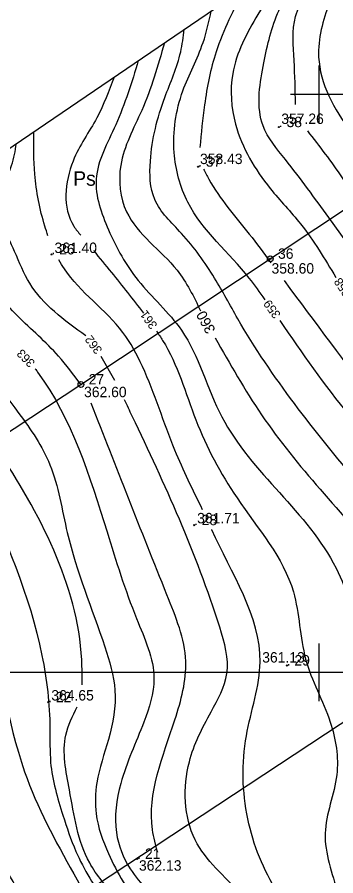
# Model space of a CAD drawing. Extents: x 4632591 to 4651936, y 5351032 to 5369988.
# Drawn here: x 4638423.8 to 4638451.4, y 5357982.4 to 5358056.7 of the extents above; entities that cross this region are included whole.
import ezdxf

# ---------------------------------------------------------------- set-up
doc = ezdxf.new("R2010")
doc.units = 0
for name, color, linetype in [('EDZPD_219', 7, 'Continuous'), ('EDZPP_202', 7, 'Continuous'), ('EKLPK_209', 7, 'Continuous'), ('Warstwa 40', 7, 'Continuous'), ('Warstwa 60', 7, 'Continuous'), ('Warstwa 62', 7, 'Continuous'), ('WUKPS_403', 7, 'Continuous'), ('WWRPH_811', 7, 'Continuous'), ('WWRPH_812', 7, 'Continuous'), ('WWRPH_814', 7, 'Continuous')]:
    doc.layers.add(name, color=color, linetype=linetype)

msp = doc.modelspace()

# ---------------------------------------------------------------- linework, layer by layer
at = {"layer": 'EDZPD_219'}
for p, q in [((4638429.37, 5358024.9), (4638519.216149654, 5358084.48679968)), ((4638419.0200000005, 5358018.09), (4638429.37, 5358024.9)), ((4638428.49, 5357980.16), (4638470.0200000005, 5358007.53))]:
    msp.add_line(p, q, dxfattribs=at)
at = {"layer": 'EDZPP_202'}
for centre in [(4638445.76, 5358035.7700000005), (4638429.37, 5358024.9)]:
    msp.add_circle(centre, 0.25, dxfattribs=at)
at = {"layer": 'Warstwa 40'}
msp.add_line((4638385.83184923, 5358019.9472410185), (4638506.884176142, 5358102.232810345), dxfattribs=at)
at = {"layer": 'Warstwa 60'}
for p, q in [((4638450, 5358047.5), (4638450, 5358052.5)), ((4638447.5, 5358050), (4638452.5, 5358050)), ((4638450, 5358000), (4638450, 5358002.5)), ((4638400, 5358000), (4638516.95102771, 5358000)), ((4638450, 5357997.5), (4638450, 5358000))]:
    msp.add_line(p, q, dxfattribs=at)
at = {"layer": 'WUKPS_403'}
for centre in [(4638446.5, 5358047.16), (4638439.51, 5358043.74), (4638426.82, 5358036.15), (4638445.76, 5358035.770000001), (4638429.37, 5358024.9), (4638439.16, 5358012.73), (4638447.18, 5358000.59), (4638426.53, 5357997.41), (4638434.24, 5357983.86)]:
    msp.add_circle(centre, 0.045, dxfattribs=at)
at = {"layer": 'WWRPH_811'}
msp.add_line((4638432.28977861, 5358025.23095936), (4638431.11162308, 5358027.317935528), dxfattribs=at)
for points in [[(4638447.943284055, 5358049.128498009), (4638447.819581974, 5358052.914616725), (4638447.944636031, 5358056.728765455), (4638450.195609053, 5358060.480387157), (4638451.633730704, 5358062.918941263), (4638452.356480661, 5358065.167496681)], [(4638448.371201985, 5358062.458495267), (4638444.693230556, 5358056.916346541), (4638442.504784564, 5358051.789130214), (4638442.754892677, 5358047.412238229), (4638445.756190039, 5358041.847332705), (4638448.38232523, 5358038.783508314), (4638451.428718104, 5358034.16460043)], [(4638445.308489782, 5358032.232813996), (4638443.942906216, 5358034.093981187), (4638438.628108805, 5358040.659319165), (4638437.440095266, 5358044.973684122), (4638438.190419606, 5358050.2884815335), (4638439.9411764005, 5358054.477792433), (4638440.652073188, 5358057.211401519)], [(4638432.23553517, 5358051.490242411), (4638430.749703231, 5358047.974981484), (4638428.686311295, 5358044.223359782), (4638428.748838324, 5358038.595927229), (4638429.357771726, 5358037.804378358)], [(4638453.640698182, 5358040.236259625), (4638452.008892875, 5358042.78523813), (4638449.001145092, 5358046.840352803)], [(4638429.782204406, 5358029.099654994), (4638424.9346895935, 5358033.656291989), (4638423.621621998, 5358036.407481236), (4638422.308554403, 5358040.9719543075), (4638423.3715138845, 5358043.848197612), (4638423.786941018, 5358045.747293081)], [(4638430.451593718, 5358036.481513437), (4638432.000243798, 5358034.594197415), (4638434.791453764, 5358031.080800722)], [(4638477.10710023, 5357993.336660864), (4638474.581150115, 5357998.641156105), (4638466.702744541, 5358006.206926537), (4638460.950257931, 5358011.5217239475), (4638456.573365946, 5358017.52431867), (4638452.634163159, 5358022.213845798), (4638446.6097368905, 5358030.42932701)], [(4638435.92321611, 5358029.499414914), (4638436.439662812, 5358028.716656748), (4638439.315906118, 5358021.8386836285), (4638442.879946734, 5358015.085764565), (4638447.757054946, 5358006.957250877), (4638448.820014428, 5358001.142237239), (4638450.945933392, 5357995.702385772), (4638451.508676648, 5357991.137912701), (4638450.508244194, 5357986.073223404), (4638451.571203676, 5357980.88348005), (4638452.294395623, 5357976.634775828)], [(4638425.399731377, 5358026.263207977), (4638425.622486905, 5358025.9654675), (4638431.625081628, 5358012.146994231), (4638434.188689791, 5358004.643750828), (4638435.689338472, 5357999.454007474), (4638434.813960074, 5357995.702385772), (4638432.813095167, 5357990.387588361), (4638432.437932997, 5357986.1357504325), (4638433.625946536, 5357983.009399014), (4638436.939879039, 5357979.570412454), (4638441.629406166, 5357975.631209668), (4638443.255108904, 5357974.2556150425), (4638446.066759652, 5357972.442840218)], [(4638429.47612731, 5357998.926286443), (4638429.436635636, 5358001.079710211), (4638422.120973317, 5358019.337602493), (4638418.413128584, 5358024.772220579)], [(4638447.811671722, 5357973.617372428), (4638443.192581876, 5357980.820953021), (4638439.253379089, 5357985.510480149), (4638438.753162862, 5357992.263399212), (4638440.628973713, 5357996.577764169), (4638442.0045683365, 5357999.891696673), (4638441.379298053, 5358003.893426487), (4638433.813527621, 5358022.15131877), (4638433.134592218, 5358023.574891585)], [(4638440.607069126, 5357973.345618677), (4638439.9411764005, 5357973.755398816), (4638435.8143925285, 5357977.3194394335), (4638432.437932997, 5357980.570844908), (4638430.1244329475, 5357983.509615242), (4638428.373676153, 5357989.824845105), (4638428.0610410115, 5357994.576899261), (4638429.048540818, 5357997.0180439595)]]:
    msp.add_spline(points, degree=3, dxfattribs=at)
at = {"layer": 'WWRPH_812'}
for points in [[(4638455.511596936, 5358067.312193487), (4638453.196906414, 5358062.856414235), (4638450.883406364, 5358057.916778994), (4638449.945500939, 5358053.227251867), (4638452.696690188, 5358046.786967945), (4638456.198203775, 5358042.597657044), (4638465.308231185, 5358026.795056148)], [(4638484.967158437, 5357998.627409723), (4638482.3970286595, 5358003.01804809), (4638479.7708934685, 5358007.144831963), (4638472.955447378, 5358013.022372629), (4638466.702744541, 5358017.5868457), (4638462.88859581, 5358020.775724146), (4638458.69928491, 5358027.341062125), (4638450.820879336, 5358039.34625157), (4638447.069257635, 5358044.348413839), (4638445.130919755, 5358047.287184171), (4638445.130919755, 5358052.414400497), (4638446.381460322, 5358056.978873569), (4638448.507379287, 5358060.855549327), (4638450.258136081, 5358063.606738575), (4638450.349313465, 5358063.803120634)], [(4638443.521665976, 5358059.162013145), (4638441.066662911, 5358053.664941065), (4638440.066230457, 5358049.100467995), (4638439.67118118, 5358045.396436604)], [(4638470.403249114, 5357988.8241761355), (4638469.266352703, 5357995.327223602), (4638466.014947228, 5358002.017615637), (4638462.951122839, 5358006.081872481), (4638458.261595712, 5358010.833926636), (4638453.3844874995, 5358016.336305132), (4638442.942473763, 5358030.592467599), (4638440.941608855, 5358034.093981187), (4638438.06536555, 5358037.970656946), (4638435.751865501, 5358040.909427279), (4638435.37670333, 5358044.223359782), (4638436.627243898, 5358049.725738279), (4638438.002838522, 5358053.664941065), (4638438.3027634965, 5358055.614453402)], [(4638434.334201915, 5358052.916815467), (4638432.375405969, 5358047.349711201), (4638430.687176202, 5358042.660184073), (4638431.750135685, 5358038.283292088), (4638434.313743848, 5358033.906400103), (4638438.06536555, 5358029.592035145), (4638441.566879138, 5358022.088791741), (4638451.44614962, 5358009.020642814), (4638453.884703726, 5358002.7054129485), (4638456.323257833, 5357996.827872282), (4638457.0110551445, 5357990.637696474), (4638457.386217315, 5357985.322899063), (4638457.723256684, 5357983.885001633)], [(4638426.514896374, 5358037.759625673), (4638426.247757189, 5358038.59592723), (4638425.372378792, 5358043.097873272), (4638425.281227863, 5358046.763037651)], [(4638429.324693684, 5358024.943127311), (4638427.435770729, 5358027.341062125), (4638423.871730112, 5358030.842575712), (4638421.058013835, 5358034.719251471), (4638420.620324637, 5358038.595927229), (4638421.3081219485, 5358042.5351300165), (4638421.218281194, 5358044.001241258)], [(4638439.987955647, 5358043.539083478), (4638440.441392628, 5358042.660184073), (4638443.942906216, 5358037.908129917), (4638445.793849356, 5358035.436805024)], [(4638416.659635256, 5358040.902492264), (4638416.24343265, 5358038.345819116), (4638416.431013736, 5358033.406183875), (4638418.369351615, 5358029.77961623), (4638423.996784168, 5358022.4014268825), (4638426.685446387, 5358017.96200787), (4638428.186095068, 5358012.084467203), (4638431.437500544, 5358002.205196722), (4638432.31287894, 5357998.45357502), (4638431.750135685, 5357994.201737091), (4638430.749703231, 5357990.450115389), (4638430.687176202, 5357987.76145317), (4638431.750135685, 5357984.32246661), (4638434.626378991, 5357979.632939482), (4638437.752730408, 5357976.69416915), (4638441.316771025, 5357974.505723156), (4638445.178855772, 5357971.8451758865)], [(4638439.891763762, 5358014.070288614), (4638437.502622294, 5358019.212548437), (4638434.688906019, 5358026.4656837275), (4638433.000676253, 5358029.40445406), (4638427.935986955, 5358034.906832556), (4638427.466138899, 5358035.672052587)], [(4638434.3930733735, 5357964.585068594), (4638430.312014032, 5357968.127966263), (4638428.436203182, 5357971.441898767), (4638424.997216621, 5357979.195250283), (4638421.745811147, 5357985.447953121), (4638420.557797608, 5357991.20043973), (4638420.432743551, 5357998.140939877), (4638413.429716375, 5358015.64850782), (4638410.115783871, 5358020.025399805), (4638407.677229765, 5358024.4022917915), (4638406.614270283, 5358028.716656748), (4638405.8014189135, 5358032.343224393), (4638405.8014189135, 5358033.521597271)], [(4638446.951934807, 5358033.890704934), (4638455.010190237, 5358023.151751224), (4638460.887730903, 5358015.523453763), (4638464.951987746, 5358010.896453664), (4638468.8911905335, 5358008.145264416), (4638472.83039332, 5358004.143534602), (4638475.331474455, 5358001.267291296), (4638479.083096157, 5357997.265561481), (4638480.929096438, 5357995.909316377)], [(4638436.017819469, 5357984.400282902), (4638435.564284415, 5357986.385858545), (4638437.502622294, 5357995.889966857), (4638438.440527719, 5358000.954656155), (4638436.814824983, 5358006.707142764), (4638430.257343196, 5358023.276343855)], [(4638420.629971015, 5358016.4947545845), (4638425.997649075, 5358001.454872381), (4638426.685446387, 5357995.139642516), (4638426.747973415, 5357992.200872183), (4638427.810932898, 5357987.636399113), (4638428.936419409, 5357984.510047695), (4638430.1244329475, 5357982.196547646), (4638431.500027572, 5357980.133155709), (4638433.250784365, 5357977.8821826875), (4638438.503054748, 5357973.880452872), (4638440.691500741, 5357972.379804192), (4638442.817419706, 5357970.754101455), (4638443.163431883, 5357970.488557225)], [(4638450.743102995, 5357975.590572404), (4638446.381460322, 5357980.9460070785), (4638443.81785216, 5357987.323763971), (4638443.692798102, 5357994.514372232), (4638444.880811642, 5358000.892129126), (4638440.691500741, 5358012.334575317), (4638440.676726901, 5358012.367430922)]]:
    msp.add_spline(points, degree=3, dxfattribs=at)
at = {"layer": 'WWRPH_814'}
for points in [[(4638436.597349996, 5358054.455195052), (4638434.62637899, 5358048.600251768), (4638432.813095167, 5358043.848197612), (4638433.313311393, 5358039.846467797), (4638437.69020338, 5358034.7817784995), (4638439.725095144, 5358031.278706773)], [(4638440.979502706, 5358028.942549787), (4638445.005865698, 5358022.276372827), (4638450.070554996, 5358015.836088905), (4638455.63546052, 5358009.458332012), (4638459.5746633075, 5358003.7683724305), (4638461.200366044, 5357999.641588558), (4638463.388812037, 5357990.825277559), (4638463.826501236, 5357985.447953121), (4638464.072388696, 5357984.562758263)], [(4638420.189851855, 5358009.16550997), (4638421.24559492, 5358005.331548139), (4638424.497000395, 5357991.388020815), (4638428.748838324, 5357982.571709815), (4638429.933889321, 5357980.492467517)]]:
    msp.add_spline(points, degree=3, dxfattribs=at)

# ---------------------------------------------------------------- texts
at = {"layer": 'EKLPK_209'}
msp.add_text('Ps', height=1.25, dxfattribs=at).set_placement((4638428.701943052, 5358042.089624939))
at = {"layer": 'Warstwa 62'}
for s, p in [('. 38', (4638446.5, 5358047.16)), ('. 37', (4638439.51, 5358043.74)), ('. 26', (4638426.82, 5358036.15)), ('. 36', (4638445.76, 5358035.7700000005)), ('. 27', (4638429.37, 5358024.9)), ('. 28', (4638439.16, 5358012.73)), ('. 29', (4638447.18, 5358000.59)), ('. 22', (4638426.53, 5357997.41)), ('. 21', (4638434.24, 5357983.86))]:
    msp.add_text(s, height=0.9, dxfattribs=at).set_placement(p)
at = {"layer": 'WUKPS_403'}
for s, p in [('357.26', (4638446.709727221, 5358047.435685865)), ('358.43', (4638439.67543653, 5358043.96543579)), ('361.40', (4638427.076240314, 5358036.274611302)), ('358.60', (4638445.865612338, 5358034.492590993)), ('362.60', (4638429.639848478, 5358023.800469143)), ('361.71', (4638439.425328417, 5358012.889502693)), ('361.13', (4638445.060576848, 5358000.845233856)), ('364.65', (4638426.802684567, 5357997.562564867)), ('362.13', (4638434.391902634, 5357982.845265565))]:
    msp.add_text(s, height=0.9, dxfattribs=at).set_placement(p)
at = {"layer": 'WWRPH_811'}
for s, height, rotation, p in [('358', 0.75, 123.31538640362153, (4638452.765486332, 5358032.813669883)), ('359', 0.7499999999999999, 125.79961989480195, (4638446.695559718, 5358030.953573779)), ('361', 0.75, 125.62944336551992, (4638436.019350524, 5358030.029318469)), ('362', 0.75, 126.73617690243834, (4638431.2579299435, 5358027.884177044)), ('363', 0.7499999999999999, 134.46440964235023, (4638425.44820982, 5358026.827767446))]:
    msp.add_text(s, height=height, rotation=rotation, dxfattribs=at).set_placement(p)
at = {"layer": 'WWRPH_814'}
msp.add_text('360', height=0.9, rotation=118.16591131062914, dxfattribs=at).set_placement((4638441.041592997, 5358029.606862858))

doc.saveas('drawing.dxf')
